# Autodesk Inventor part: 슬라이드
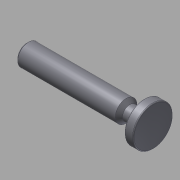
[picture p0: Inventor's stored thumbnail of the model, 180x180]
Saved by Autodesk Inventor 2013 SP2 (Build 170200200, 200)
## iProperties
Company: 한국ATC센터
Created: 2015-12
Part Number: 슬라이드
Document SubType Name: Modeling
Designer: mdu
Density: 7.86 g/cm^3
Mass: 68.0563 g
Surface Area: 34.7349 cm^2
Volume: 8.65856 cm^3
Material: 강철, 연강
Author: mdu
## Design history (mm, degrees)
sketch "스케치1"
  geometry: L1 (-35, 0)-(35, 0); L2 (35, 0)-(35, 11); L3 (35, 11)-(30, 11); L4 (30, 11)-(30, 4); L5 (30, 4)-(22, 4); L6 (22, 4)-(20, 6); L7 (20, 6)-(-35, 6); L8 (-35, 6)-(-35, 0); 1 further point
  constraints: 16 end point, 4 parallel, 2 midpoint, 2 perpendicular, 1 horizontal
  dimensions: "d0" = 70 distance of L1.start L1.end; "d1" = 12 diameter of L7 L1; "d2" = 22 diameter of L3 L1; "d3" = 5 distance of L2.end L3.end; "d4" = 8 diameter of L5 L1; "d5" = 135 deg angle of L6 L5; "d6" = 15 distance from line of L2 L6.end
revolve "회전1" sketch "스케치1" stored, may be unused: angle "d7" = 90 deg
chamfer "모따기1" distance "d8" = 1; stored, may be unused: second distance "d9" = 2, angle "d10" = 45 deg
fillet "모깎기1" dims "d11" = 0.5
node "솔리드1"
